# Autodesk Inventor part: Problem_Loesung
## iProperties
Created: 2010-08
Part Number: Problem_Loesung
Document SubType Name: Modeling
Designer: M.Grouls
Density: 1 g/cm^3
Author: M.Grouls
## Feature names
1. Extrusion1
2. Extrusion2
3. Extrusion3
